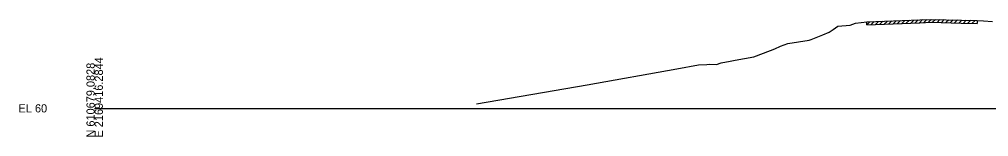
# Model space of a CAD drawing. Extents: x -26 to 6803, y -10 to 19606.
# Drawn here: x 1974.3 to 2305.1, y 8990.3 to 9030.5 of the extents above; entities that cross this region are included whole.
import ezdxf

# ---------------------------------------------------------------- set-up
doc = ezdxf.new("R2010")
doc.units = 0
for name, color, linetype in [('RD_GPK_XS_Cell', 7, 'Continuous'), ('RD_XS_ExGround', 7, 'Continuous'), ('RD_XS_ExPaveRet', 7, 'Continuous')]:
    doc.layers.add(name, color=color, linetype=linetype)

msp = doc.modelspace()

# ---------------------------------------------------------------- linework, layer by layer
at = {"layer": 'RD_GPK_XS_Cell'}
msp.add_line((2000, 9000), (2400, 9000), dxfattribs=at)
at = {"layer": 'RD_XS_ExGround'}
msp.add_lwpolyline([(2130.32, 9001.56), (2168.09, 9008.09), (2198.71, 9013.47), (2206.1, 9014.85), (2208.91, 9015.05), (2209.93, 9015.07), (2212.26, 9015.05), (2213.83, 9015.52), (2216.86, 9016.19), (2218.62, 9016.52), (2224.99, 9017.62), (2228.32, 9018.88), (2232.12, 9020.38), (2234.07, 9021.26), (2236.53, 9022.15), (2243.84, 9023.38), (2244.55, 9023.54), (2245.16, 9023.78), (2248.56, 9025.15), (2250.71, 9026.08), (2252.05, 9026.93), (2253.64, 9028.07), (2257.89, 9028.5), (2259.69, 9029.2), (2263.51, 9029.6), (2281.63, 9030.31), (2285.55, 9030.46), (2295.78, 9030.2), (2301.16, 9030.08), (2303.34, 9029.93), (2306.47, 9029.71)], dxfattribs=at)
at = {"layer": 'RD_XS_ExPaveRet'}
for p, q in [((2263.5, 9028.6), (2264.55, 9029.65)), ((2263.5, 9028.6), (2263.5, 9029.6)), ((2263.5, 9028.6), (2263.51, 9028.6)), ((2263.51, 9028.6), (2281.63, 9029.31)), ((2265, 9028.66), (2266.05, 9029.7)), ((2266.5, 9028.72), (2267.55, 9029.76)), ((2268, 9028.78), (2269.05, 9029.82)), ((2269.5, 9028.84), (2270.55, 9029.88)), ((2271, 9028.9), (2272.05, 9029.94)), ((2272.5, 9028.96), (2273.55, 9030)), ((2274, 9029.01), (2275.05, 9030.05)), ((2275.5, 9029.07), (2276.55, 9030.11)), ((2277, 9029.13), (2278.05, 9030.17)), ((2278.5, 9029.19), (2279.55, 9030.23)), ((2280, 9029.25), (2281.05, 9030.29)), ((2281.5, 9029.31), (2282.55, 9030.35)), ((2281.63, 9029.31), (2285.55, 9029.46)), ((2283, 9029.36), (2284.05, 9030.41)), ((2284.5, 9029.42), (2285.55, 9030.46)), ((2285.55, 9029.46), (2295.78, 9029.2)), ((2286, 9029.45), (2286.98, 9030.43)), ((2287.5, 9029.41), (2288.48, 9030.39)), ((2289, 9029.38), (2289.98, 9030.35)), ((2290.5, 9029.34), (2291.48, 9030.31)), ((2292, 9029.3), (2292.98, 9030.27)), ((2293.5, 9029.26), (2294.48, 9030.24)), ((2295, 9029.22), (2295.98, 9030.2)), ((2295.78, 9029.2), (2301.16, 9029.08)), ((2296.5, 9029.19), (2297.48, 9030.16)), ((2298, 9029.15), (2298.98, 9030.13)), ((2299.5, 9029.11), (2300.48, 9030.09)), ((2301.16, 9030.08), (2301.16, 9029.08))]:
    msp.add_line(p, q, dxfattribs=at)

# ---------------------------------------------------------------- texts
at = {"layer": 'RD_GPK_XS_Cell'}
for s, p in [('N 610679.0828', (2000, 8990)), ('E 2169416.2844', (2002.8, 8990))]:
    msp.add_text(s, height=2.8, rotation=90, dxfattribs=at).set_placement(p)
msp.add_text('EL 60', height=2.8, dxfattribs=at).set_placement((1974, 8998.6))

doc.saveas('drawing.dxf')
